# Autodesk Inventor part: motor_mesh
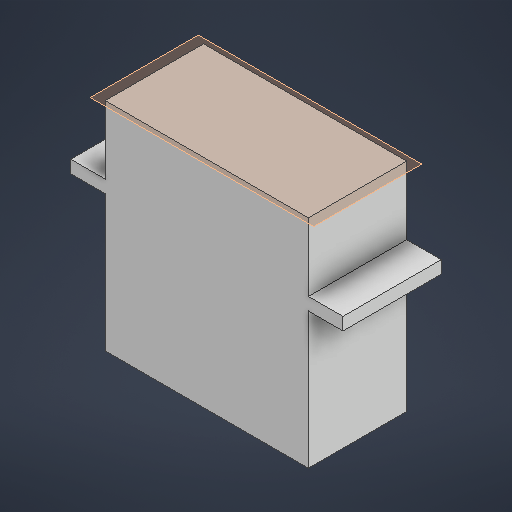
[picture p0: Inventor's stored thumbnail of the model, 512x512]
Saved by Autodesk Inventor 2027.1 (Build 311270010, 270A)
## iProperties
Created: 2026-11
Part Number: motor_mesh
Material: Generic
Document SubType Name: Modeling
Designer: djshs
Density: 1 g/cm^3
Appearance: Default
Author: djshs
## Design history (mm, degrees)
sketch "스케치1"
  geometry: L1 (20.15, 9.75)-(-20.15, 9.75); L2 (-20.15, 9.75)-(-20.15, -9.75); L3 (-20.15, -9.75)-(20.15, -9.75); L4 (20.15, -9.75)-(20.15, 9.75); L5 (20.15, 9.75)-(-20.15, -9.75); L6 (-20.15, 9.75)-(20.15, -9.75); 1 further point
  constraints: 12 end point, 2 midpoint, 2 parallel, 1 horizontal, 1 perpendicular
  dimensions: "d0" = 40.3 distance of L3.end L2.end; "d1" = 19.5 distance of L2.end L1.end
extrude "돌출1" new body sketch "스케치1" distance "d2" = 27; taper "d3" = 0 deg
sketch "스케치2"
  geometry: L1 (-27, -9.75)-(27, -9.75); L2 (27, -9.75)-(27, 9.75); L3 (27, 9.75)-(-27, 9.75); L4 (-27, 9.75)-(-27, -9.75); L5 (-27, -9.75)-(27, 9.75); L6 (27, -9.75)-(-27, 9.75); 1 further point
  constraints: 12 end point, 2 midpoint, 2 parallel, 1 horizontal, 1 perpendicular
  dimensions: "d4" = 54 distance of L3.end L2.end; "d5" = 19.5 distance of L2.end L1.end
extrude "돌출2" join sketch "스케치2" distance "d6" = 2.5; taper "d7" = 0 deg
sketch "스케치3"
  geometry: L1 (-27, -9.75)-(-20.15, -9.75) reference; L2 (20.15, 9.75)-(-20.15, 9.75); L3 (-20.15, 9.75)-(-20.15, -9.75); L4 (-20.15, -9.75)-(20.15, -9.75); L5 (20.15, -9.75)-(20.15, 9.75); L6 (20.15, 9.75)-(-20.15, -9.75); L7 (-20.15, 9.75)-(20.15, -9.75); 2 further points
  constraints: 12 end point, 2 midpoint, 2 parallel, 1 horizontal, 1 perpendicular, 1 point on line
  dimensions: "d8" = 40.3 distance of L4.end L3.end
extrude "돌출3" join sketch "스케치3" distance "d9" = 13.5; taper "d10" = 0 deg
node "작업 평면1"
sketch "스케치4"
  geometry: L1 (27, -9.75)-(27, 9.75) reference; C1 r 2.9 at (9.85, 0); C2 r 1.5 at (9.85, 0); 2 further points
  constraints: 2 centre point, 2 coincident
  dimensions: "d12" = 17.15 distance from line of L1 point (9.85, 0); "d13" = 5.8 diameter of C1; "d14" = 3 diameter of C2
extrude "돌출4" join sketch "스케치4" distance "d15" = 3; taper "d16" = 0 deg
node "솔리드1"
other parameters: "d11" = 0
